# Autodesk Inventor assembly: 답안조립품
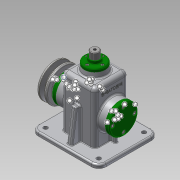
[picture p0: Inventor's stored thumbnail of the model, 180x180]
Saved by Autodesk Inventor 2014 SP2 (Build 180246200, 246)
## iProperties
Created: 2016-08
Part Number: 답안조립품
Document SubType Name: Assembly
Designer: user
Author: user
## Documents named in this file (19)
- C:\Users\user\Desktop\460820V1017\답안조립품.iam
- C:\Users\user\Desktop\460820V1017\본체.ipt
- C:\Users\user\Desktop\460820V1017\V-벨트풀리.ipt
- C:\Users\user\Desktop\460820V1017\고정핀.ipt
- C:\Users\user\Desktop\460820V1017\뒤커버.ipt
- C:\Users\user\Desktop\460820V1017\링크.ipt
- C:\Users\user\Desktop\460820V1017\멈춤링 6 x 5.ipt
- C:\Users\user\Desktop\460820V1017\멈춤링 15 x 1.ipt
- C:\Users\user\Desktop\460820V1017\베어링 15 x 35 x 11.ipt
- C:\Users\user\Desktop\460820V1017\볼트 M3 x 8.ipt
- C:\Users\user\Desktop\460820V1017\볼트 M4 x 10.ipt
- C:\Users\user\Desktop\460820V1017\볼트 M6 x 12.ipt
- C:\Users\user\Desktop\460820V1017\상부부시.ipt
- C:\Users\user\Desktop\460820V1017\슬라이드바.ipt
- C:\Users\user\Desktop\460820V1017\앞커버.ipt
- C:\Users\user\Desktop\460820V1017\오일실 15 25 7.ipt
- C:\Users\user\Desktop\460820V1017\와셔.ipt
- C:\Users\user\Desktop\460820V1017\키 5 x 5 x 14.ipt
- C:\Users\user\Desktop\460820V1017\편심축.ipt
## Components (15 placed, 5 different names)
1. V-벨트풀리:1 — 각도:1, 구동
2. 고정핀:1
3. ISO 4018 M6 x 12:1 — 각도:2
4. ISO 4762 M3 x 8:1 — 강체:3
5. ISO 4762 M3 x 8:2
6. ISO 4762 M3 x 8:3
7. ISO 4762 M3 x 8:4
8. ISO 4762 M4 x 10:1 — 강체:2
9. ISO 4762 M4 x 10:3
10. ISO 4762 M4 x 10:4
11. ISO 4762 M4 x 10:5
12. ISO 4762 M4 x 10:2 — 강체:1
13. ISO 4762 M4 x 10:6
14. ISO 4762 M4 x 10:7
15. ISO 4762 M4 x 10:8
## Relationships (6: Angle 3, WeldJoint 3)
- 각도:1 [Angle]: V-벨트풀리:1
- 각도:2 [Angle]: ISO 4018 M6 x 12:1
- 강체:1 [WeldJoint]: ISO 4762 M4 x 10:2
- 강체:2 [WeldJoint]: ISO 4762 M4 x 10:1
- 강체:3 [WeldJoint]: ISO 4762 M3 x 8:1
- 구동 [Angle]: V-벨트풀리:1
